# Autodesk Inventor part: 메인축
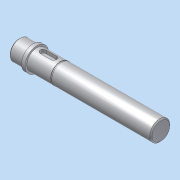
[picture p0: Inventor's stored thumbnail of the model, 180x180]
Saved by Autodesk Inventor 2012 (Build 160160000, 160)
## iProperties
Company: 한국ATC센터
Created: 2014-12
Part Number: 메인축
Document SubType Name: Modeling
Designer: KYOUNG IL JANG
Density: 1 g/cm^3
Mass: 27.2374 g
Surface Area: 71.2962 cm^2
Volume: 27.2374 cm^3
Material: 기본값
Author: KYOUNG IL JANG
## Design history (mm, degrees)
sketch "스케치1"
  geometry: L1 (0, 0)-(120, 0); L2 (0, 0)-(0, 7.5); L3 (1, 8.5)-(12, 8.5); L4 (12, 8.5)-(12, 10); L5 (12, 10)-(15, 10); L6 (15, 10)-(15, 8.5); L7 (15, 8.5)-(119, 8.5); L8 (120, 0)-(120, 7.5); L9 (1, 8.5)-(0, 7.5); L10 (119, 8.5)-(120, 7.5); 2 further points
  constraints: 20 end point, 4 point on line, 3 parallel, 3 perpendicular, 1 collinear, 1 horizontal
  dimensions: "d0" = 12 distance of point (0, 8.5) L3.end; "d1" = 17 diameter of L3 L1; "d2" = 20 diameter of L5 L1; "d3" = 17 diameter of L7 L1; "d4" = 3 distance of L4.end L5.end; "d5" = 120 distance of L1.start L1.end; "d6" = 1 distance of L3.start point (0, 8.5); "d7" = 1 distance of L2.end point (0, 8.5) (= d6); "d8" = 1 distance of L7.end point (120, 8.5) (= d6); "d9" = 1 distance of L8.end point (120, 8.5) (= d8)
revolve "회전1" sketch "스케치1" stored, may be unused: angle "d10" = 90 deg
node "작업 평면1"
sketch "스케치2"
  geometry: L1 (-46.5, 2.5)-(-37.5, 2.5); L2 (-37.5, -2.5)-(-46.5, -2.5); L3 (-52, -10)-(-52, 10) reference; A1 r 2.5 centre (-37.5, 0) between (-37.5, -2.5) and (-37.5, 2.5); A2 r 2.5 centre (-46.5, 0) between (-46.5, 2.5) and (-46.5, -2.5); 1 further point
  constraints: 4 end point, 4 point on circle, 4 tangent, 2 centre point, 1 horizontal, 1 horizontal alignment, 1 parallel
  dimensions: "d11" = 5 distance between parallel lines of L2 L1; "d12" = 3 distance edge to line of A2 L3; "d13" = 14 dimension on A1 A2
extrude "돌출1" cut sketch "스케치2" distance "d14" = 3; taper "d15" = 0 deg
sketch "스케치3"
  geometry: L1 (15, 8.5)-(119, 8.5) reference; L2 (35, 8.5)-(36.15, 8.5); L3 (36.15, 8.5)-(36.15, 8.1); L4 (36.15, 8.1)-(35, 8.1); L5 (35, 8.1)-(35, 8.5); L6 (15, -10)-(15, 10) reference; L7 (-23.8, 0)-(142.8, 0) reference; 1 further point
  constraints: 8 end point, 2 parallel, 1 horizontal, 1 perpendicular, 1 point on line
  dimensions: "d16" = 1.15 distance of L3.end L4.end; "d17" = 20 distance between parallel lines of L5 L6; "d18" = 8.1 distance from line of L4 point (0, 0)
revolve "회전2" sketch "스케치3" stored, may be unused: angle "d19" = 90 deg
node "솔리드1"
